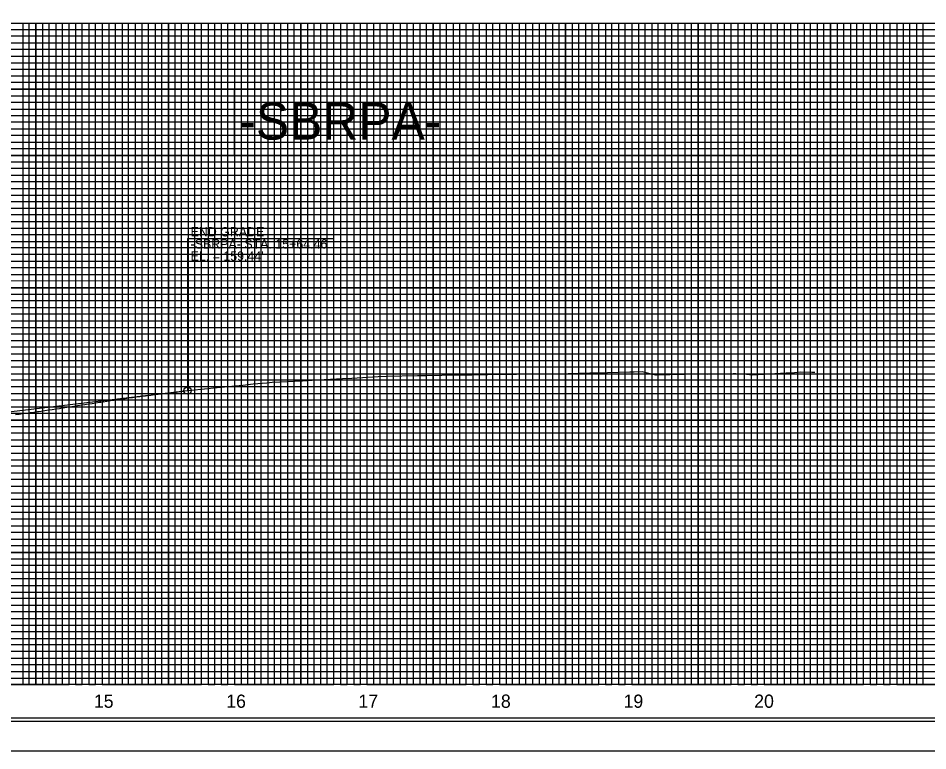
# Model space of a CAD drawing. Extents: x 573468 to 580768, y -57414 to -51768.
# Drawn here: x 579332 to 580019, y -57414 to -56860 of the extents above; entities that cross this region are included whole.
import ezdxf

# ---------------------------------------------------------------- set-up
doc = ezdxf.new("R2010")
doc.units = 0
for name, color, linetype in [('Exist Vertical Profile Ground Line', 7, 'Continuous'), ('Exist Vertical Profile Horizontal Axis Label Major', 7, 'Continuous'), ('Prop Grid Mask', 7, 'Continuous'), ('Prop PFL Text', 7, 'Continuous'), ('Prop Vertical Profile Grade', 7, 'Continuous'), ('Prop VPI Label', 7, 'Continuous'), ('Sheet Cutting Line CELL', 7, 'Continuous'), ('Sheet DOT Grid CELL', 7, 'Continuous'), ('Sheet Layout Profile Border Port 2', 7, 'Continuous'), ('Sheet Plot Border Inside CELL', 7, 'Continuous'), ('Sheet Plot Border Outside CELL', 7, 'Continuous'), ('Sheet Profile CELL', 7, 'Continuous'), ('Sheet Profile Grid Major CELL', 7, 'Continuous'), ('Sheet Profile Grid Middle CELL', 7, 'Continuous'), ('Sheet Profile Grid Minor CELL', 7, 'Continuous')]:
    doc.layers.add(name, color=color, linetype=linetype)

msp = doc.modelspace()

# ---------------------------------------------------------------- linework, layer by layer
at = {"layer": 'Exist Vertical Profile Ground Line'}
for points in [[(579365.05, -57154.41), (579365.65, -57154.32), (579368.42, -57153.92), (579371.18, -57153.52), (579372.22, -57153.37), (579373.95, -57153.08), (579376.71, -57152.63), (579379.57, -57152.17), (579382.24, -57151.77), (579385.01, -57151.36), (579387.77, -57150.95), (579390.54, -57150.54), (579393.31, -57150.13), (579394.3, -57149.99), (579396.07, -57149.71), (579398.84, -57149.28), (579400.55, -57149.01), (579401.6, -57148.86), (579404.37, -57148.47), (579407.13, -57148.07), (579409.9, -57147.68), (579412.66, -57147.29), (579415.43, -57146.91), (579418.19, -57146.52), (579420.96, -57146.14), (579423.72, -57145.75), (579426.49, -57145.37), (579427.84, -57145.19), (579429.26, -57145.02), (579432.02, -57144.69), (579434.79, -57144.36), (579437.55, -57144.04), (579440.32, -57143.71), (579443.08, -57143.39), (579445.85, -57143.07), (579448.61, -57142.76), (579449.25, -57142.68), (579451.38, -57142.41), (579454.14, -57142.05), (579456.91, -57141.69), (579457.5, -57141.61), (579459.67, -57141.37), (579475.09, -57139.65), (579479.32, -57139.11), (579501.55, -57137.23), (579509.31, -57136.33), (579519.62, -57135.47), (579523.72, -57134.99), (579546.45, -57133.82), (579553.68, -57133.4), (579576.75, -57132.21), (579583.65, -57131.8), (579603.7, -57130.77), (579609.88, -57130.41), (579633.45, -57130), (579639.84, -57129.88), (579663.64, -57129.47), (579669.8, -57129.36), (579674.4, -57129.28), (579698.51, -57129), (579704.4, -57128.93), (579708.02, -57128.88), (579732.32, -57128.6), (579733.3, -57128.59), (579738.84, -57128.53), (579763.46, -57127.85), (579768.59, -57127.8), (579793.62, -57127.11), (579796.85, -57127.07), (579803.01, -57126.9), (579811.94, -57129.08), (579813.1, -57129.38), (579813.92, -57129.39), (579822.16, -57129.17), (579823.92, -57129.11), (579833.6, -57128.82), (579834.9, -57128.78), (579845.06, -57128.3), (579845.71, -57128.3), (579851.29, -57128.76), (579852, -57128.82), (579856.05, -57128.57), (579857.12, -57128.56), (579861.44, -57128.6), (579862.9, -57128.69), (579868.03, -57128.62), (579871.83, -57128.49), (579873.8, -57128.35), (579877.34, -57128.57), (579879.8, -57128.61), (579881.86, -57128.86), (579884.16, -57129.11), (579886.28, -57129.31), (579911.68, -57127.88), (579913.57, -57127.87), (579915.66, -57127.77), (579922.19, -57127.14), (579931.1, -57127.47), (579933.49, -57127.47)], [(579329.7, -57159.39), (579332.47, -57159.03), (579335.23, -57158.66), (579338, -57158.3), (579340.76, -57157.93), (579341.43, -57157.85), (579343.53, -57157.55), (579346.29, -57157.17), (579347.15, -57157.05), (579349.06, -57156.76), (579351.82, -57156.35), (579354.59, -57155.94), (579357.36, -57155.53), (579360.12, -57155.13), (579362.89, -57154.73), (579365.05, -57154.41)]]:
    msp.add_lwpolyline(points, dxfattribs=at)
at = {"layer": 'Prop Grid Mask'}
msp.add_lwpolyline([(579495.21, -56913.55), (579645.21, -56913.55), (579645.21, -56963.55), (579495.21, -56963.55)], close=True, dxfattribs=at)
at = {"layer": 'Prop PFL Text'}
for q in [(579570.38, -57026.26), (579459.67, -57141.35)]:
    msp.add_line((579459.67, -57026.26), q, dxfattribs=at)
at = {"layer": 'Prop Vertical Profile Grade'}
msp.add_line((579305.21, -57159.61), (579459.67, -57141.35), dxfattribs=at)
at = {"layer": 'Prop VPI Label'}
msp.add_circle((579459.67, -57141.35), 2.75, dxfattribs=at)
at = {"layer": 'Sheet Cutting Line CELL'}
msp.add_line((578678.21, -57413.55), (580362.21, -57413.55), dxfattribs=at)
at = {"layer": 'Sheet DOT Grid CELL'}
for p, q in [((578845.21, -56863.55), (580345.1, -56863.55)), ((579345.21, -56863.55), (579345.21, -57363.55)), ((579395.21, -56863.55), (579395.21, -57363.55)), ((579445.21, -56863.55), (579445.21, -57363.55)), ((579495.21, -56863.55), (579495.21, -57363.55)), ((579545.21, -56863.55), (579545.21, -57363.55)), ((579595.21, -56863.55), (579595.21, -57363.55)), ((579645.21, -56863.55), (579645.21, -57363.55)), ((579695.21, -56863.55), (579695.21, -57363.55)), ((579745.21, -56863.55), (579745.21, -57363.55)), ((579795.21, -56863.55), (579795.21, -57363.55)), ((579845.21, -56863.55), (579845.21, -57363.55)), ((579895.21, -56863.55), (579895.21, -57363.55)), ((579945.21, -56863.55), (579945.21, -57363.55)), ((579995.21, -56863.55), (579995.21, -57363.55)), ((578845.21, -56913.55), (580345.1, -56913.55)), ((578845.21, -56963.55), (580345.1, -56963.55)), ((578845.21, -57013.55), (580345.1, -57013.55)), ((578845.21, -57063.55), (580345.1, -57063.55)), ((578845.21, -57113.55), (580345.1, -57113.55)), ((578845.21, -57163.55), (580345.1, -57163.55)), ((578845.21, -57213.55), (580345.1, -57213.55)), ((578845.21, -57263.55), (580345.1, -57263.55)), ((578845.21, -57313.55), (580345.1, -57313.55))]:
    msp.add_line(p, q, dxfattribs=at)
at = {"layer": 'Sheet Layout Profile Border Port 2'}
msp.add_lwpolyline([(578895.21, -56863.55), (580295.21, -56863.55), (580295.21, -57363.55), (578895.21, -57363.55)], close=True, dxfattribs=at)
at = {"layer": 'Sheet Plot Border Inside CELL'}
msp.add_lwpolyline([(578691.21, -57391.1), (580357.71, -57391.1), (580357.71, -56336), (578691.21, -56336)], close=True, dxfattribs=at)
at = {"layer": 'Sheet Plot Border Outside CELL'}
msp.add_lwpolyline([(578678.21, -57413.55), (580362.21, -57413.55), (580362.21, -56313.55), (578678.21, -56313.55)], close=True, dxfattribs=at)
at = {"layer": 'Sheet Profile CELL'}
for p, q in [((578845.21, -56863.55), (580345.21, -56863.55)), ((580345.21, -57363.55), (578845.21, -57363.55)), ((578845.21, -57388.55), (580345.21, -57388.55))]:
    msp.add_line(p, q, dxfattribs=at)
msp.add_lwpolyline([(580345.21, -56338.55), (578845.21, -56338.55), (578845.21, -57388.55), (580345.21, -57388.55)], close=True, dxfattribs=at)
at = {"layer": 'Sheet Profile Grid Major CELL'}
for p, q in [((579345.21, -56863.55), (579395.21, -56863.55)), ((579445.21, -56863.55), (579495.21, -56863.55)), ((579545.21, -56863.55), (579595.21, -56863.55)), ((579645.21, -56863.55), (579695.21, -56863.55)), ((579745.21, -56863.55), (579795.21, -56863.55)), ((579845.21, -56863.55), (579895.21, -56863.55)), ((579945.21, -56863.55), (579995.21, -56863.55))]:
    msp.add_line(p, q, dxfattribs=at)
for points in [[(579295.21, -57363.55), (579345.21, -57363.55), (579345.21, -56863.55), (579395.21, -56863.55), (579395.21, -57363.55), (579445.21, -57363.55), (579445.21, -56863.55), (579495.21, -56863.55), (579495.21, -57363.55), (579545.21, -57363.55), (579545.21, -56863.55), (579595.21, -56863.55), (579595.21, -57363.55), (579645.21, -57363.55), (579645.21, -56863.55), (579695.21, -56863.55), (579695.21, -57363.55), (579745.21, -57363.55), (579745.21, -56863.55), (579795.21, -56863.55), (579795.21, -57363.55), (579845.21, -57363.55), (579845.21, -56863.55), (579895.21, -56863.55), (579895.21, -57363.55), (579945.21, -57363.55), (579945.21, -56863.55), (579995.21, -56863.55), (579995.21, -57363.55), (580045.21, -57363.55)], [(580345.21, -56913.55), (578845.21, -56913.55)], [(580345.21, -56963.55), (578845.21, -56963.55), (578845.21, -57013.55), (580345.21, -57013.55)], [(580345.21, -57063.55), (578845.21, -57063.55), (578845.21, -57113.55), (580345.21, -57113.55)], [(580345.21, -57163.55), (578845.21, -57163.55), (578845.21, -57213.55), (580345.21, -57213.55)], [(580345.21, -57263.55), (578845.21, -57263.55), (578845.21, -57263.55), (578845.21, -57313.55), (580345.21, -57313.55)], [(580345.21, -57363.55), (578845.21, -57363.55)]]:
    msp.add_lwpolyline(points, dxfattribs=at)
at = {"layer": 'Sheet Profile Grid Middle CELL'}
for points in [[(579320.21, -57363.55), (579370.21, -57363.55), (579370.21, -56863.55), (579420.21, -56863.55), (579420.21, -57363.55), (579470.21, -57363.55), (579470.21, -57363.55), (579470.21, -56863.55), (579520.21, -56863.55), (579520.21, -57363.55), (579570.21, -57363.55), (579570.21, -56863.55), (579620.21, -56863.55), (579620.21, -57363.55), (579670.21, -57363.55), (579670.21, -56863.55), (579720.21, -56863.55), (579720.21, -57363.55), (579770.21, -57363.55), (579770.21, -56863.55), (579820.21, -56863.55), (579820.21, -57363.55), (579870.21, -57363.55), (579870.21, -56863.55), (579920.21, -56863.55), (579920.21, -57363.55), (579970.21, -57363.55), (579970.21, -56863.55), (580020.21, -56863.55)], [(578845.21, -56888.55), (580345.21, -56888.55)], [(580345.21, -56938.55), (578845.21, -56938.55), (578845.21, -56988.55), (580345.21, -56988.55)], [(580345.21, -57038.55), (578845.21, -57038.55), (578845.21, -57088.55), (580345.21, -57088.55)], [(580345.21, -57138.55), (578845.21, -57138.55), (578845.21, -57188.55), (580345.21, -57188.55)], [(580345.21, -57238.55), (578845.21, -57238.55), (578845.21, -57288.55), (580345.21, -57288.55)], [(580345.21, -57338.55), (578845.21, -57338.55)]]:
    msp.add_lwpolyline(points, dxfattribs=at)
at = {"layer": 'Sheet Profile Grid Minor CELL'}
for p, q in [((578895.21, -56868.55), (580295.21, -56868.55)), ((580295.21, -56873.55), (578895.21, -56873.55)), ((578895.21, -56878.55), (580295.21, -56878.55)), ((580295.21, -56883.55), (578895.21, -56883.55)), ((578895.21, -56893.55), (580295.21, -56893.55)), ((580295.21, -56898.55), (578895.21, -56898.55)), ((578895.21, -56903.55), (580295.21, -56903.55)), ((580295.21, -56908.55), (578895.21, -56908.55)), ((578895.21, -56918.55), (580295.21, -56918.55)), ((580295.21, -56923.55), (578895.21, -56923.55)), ((578895.21, -56928.55), (580295.21, -56928.55)), ((580295.21, -56933.55), (578895.21, -56933.55)), ((578895.21, -56943.55), (580295.21, -56943.55)), ((580295.21, -56948.55), (578895.21, -56948.55)), ((578895.21, -56953.55), (580295.21, -56953.55)), ((580295.21, -56958.55), (578895.21, -56958.55)), ((578895.21, -56968.55), (580295.21, -56968.55)), ((580295.21, -56973.55), (578895.21, -56973.55)), ((578895.21, -56978.55), (580295.21, -56978.55)), ((580295.21, -56983.55), (578895.21, -56983.55)), ((578895.21, -56993.55), (580295.21, -56993.55)), ((580295.21, -56998.55), (578895.21, -56998.55)), ((578895.21, -57003.55), (580295.21, -57003.55)), ((580295.21, -57008.55), (578895.21, -57008.55)), ((578895.21, -57018.55), (580295.21, -57018.55)), ((580295.21, -57023.55), (578895.21, -57023.55)), ((578895.21, -57028.55), (580295.21, -57028.55)), ((580295.21, -57033.55), (578895.21, -57033.55)), ((578895.21, -57043.55), (580295.21, -57043.55)), ((580295.21, -57048.55), (578895.21, -57048.55)), ((578895.21, -57053.55), (580295.21, -57053.55)), ((580295.21, -57058.55), (578895.21, -57058.4)), ((578895.21, -57068.55), (580295.21, -57068.55)), ((580295.21, -57073.55), (578895.21, -57073.55)), ((578895.21, -57078.55), (580295.21, -57078.55)), ((580295.21, -57083.55), (578895.21, -57083.55)), ((578895.21, -57093.55), (580295.21, -57093.55)), ((580295.21, -57098.55), (578895.21, -57098.55)), ((578895.21, -57103.55), (580295.21, -57103.55)), ((580295.21, -57108.55), (578895.21, -57108.55)), ((578895.21, -57118.55), (580295.21, -57118.55)), ((580295.21, -57123.55), (578895.21, -57123.55)), ((578895.21, -57128.55), (580295.21, -57128.55)), ((580295.21, -57133.55), (578895.21, -57133.55)), ((578895.21, -57143.55), (580295.21, -57143.55)), ((580295.21, -57148.55), (578895.21, -57148.55)), ((578895.21, -57153.55), (580295.21, -57153.55)), ((580295.21, -57158.55), (578895.21, -57158.55)), ((578895.21, -57168.55), (580295.21, -57168.55)), ((580295.21, -57173.55), (578895.21, -57173.55)), ((578895.21, -57178.55), (580295.21, -57178.55)), ((580295.21, -57183.55), (578895.21, -57183.55)), ((578895.21, -57193.55), (580295.21, -57193.55)), ((580295.21, -57198.55), (578895.21, -57198.55)), ((578895.21, -57203.55), (580295.21, -57203.55)), ((580295.21, -57208.55), (578895.21, -57208.55)), ((578895.21, -57218.55), (580295.21, -57218.55)), ((580295.21, -57223.55), (578895.21, -57223.55)), ((578895.21, -57228.55), (580295.21, -57228.55)), ((580295.21, -57233.55), (578895.21, -57233.55)), ((578895.21, -57243.55), (580295.21, -57243.55)), ((580295.21, -57248.55), (578895.21, -57248.55)), ((578895.21, -57253.55), (580295.21, -57253.55)), ((580295.21, -57258.55), (578895.21, -57258.55)), ((578895.21, -57268.55), (580295.21, -57268.55)), ((580295.21, -57273.55), (578895.21, -57273.55)), ((578895.21, -57278.55), (580295.21, -57278.55)), ((580295.21, -57283.55), (578895.21, -57283.55)), ((578895.21, -57293.55), (580295.21, -57293.55)), ((580295.21, -57298.55), (578895.21, -57298.55)), ((578895.21, -57303.55), (580295.21, -57303.55)), ((580295.21, -57308.55), (578895.21, -57308.55)), ((578895.21, -57318.55), (580295.21, -57318.55)), ((580295.21, -57323.55), (578895.21, -57323.55)), ((578895.21, -57328.55), (580295.21, -57328.55)), ((580295.21, -57333.55), (578895.21, -57333.55)), ((578895.21, -57343.55), (580295.21, -57343.55)), ((580295.21, -57348.55), (578895.21, -57348.55)), ((578895.21, -57353.55), (580295.21, -57353.55)), ((578895.21, -57358.55), (580295.21, -57358.55))]:
    msp.add_line(p, q, dxfattribs=at)
for points in [[(579330.21, -56863.55), (579335.21, -56863.55), (579335.21, -57363.55), (579340.21, -57363.55), (579340.21, -56863.55), (579350.21, -56863.55), (579350.21, -57363.55), (579355.21, -57363.55), (579355.21, -56863.55), (579360.21, -56863.55), (579360.21, -57363.55), (579365.21, -57363.55), (579365.21, -56863.55), (579375.21, -56863.55), (579375.21, -57363.55), (579380.21, -57363.55), (579380.21, -56863.55), (579385.21, -56863.55), (579385.21, -57363.55), (579390.21, -57363.55), (579390.21, -56863.55), (579400.21, -56863.55), (579400.21, -57363.55), (579405.21, -57363.55), (579405.21, -56863.55), (579410.21, -56863.55), (579410.21, -57363.55), (579415.21, -57363.55), (579415.21, -56863.55), (579425.21, -56863.55)], [(579425.21, -56863.55), (579425.21, -57363.55), (579430.21, -57363.55), (579430.21, -56863.55), (579435.21, -56863.55), (579435.21, -57363.55), (579440.21, -57363.55), (579440.21, -56863.55), (579450.21, -56863.55), (579450.21, -57363.55), (579455.21, -57363.55), (579455.21, -56863.55), (579460.21, -56863.55), (579460.21, -57363.55), (579465.21, -57363.55), (579465.21, -56863.55), (579475.21, -56863.55), (579475.21, -57363.55), (579480.21, -57363.55), (579480.21, -56863.55), (579485.21, -56863.55), (579485.21, -57363.55), (579490.21, -57363.55), (579490.21, -56863.55), (579500.21, -56863.55), (579500.21, -57363.55), (579505.21, -57363.55), (579505.21, -56863.55), (579510.21, -56863.55), (579510.21, -57363.55), (579515.21, -57363.55), (579515.21, -56863.55), (579525.21, -56863.55), (579525.21, -57363.55), (579530.21, -57363.55), (579530.21, -56863.55), (579535.21, -56863.55), (579535.21, -57363.55), (579540.21, -57363.55), (579540.21, -56863.55), (579550.21, -56863.55), (579550.21, -57363.55), (579550.21, -57363.55), (579555.21, -57363.55), (579555.21, -56863.55), (579560.21, -56863.55), (579560.21, -57363.55), (579565.21, -57363.55), (579565.21, -56863.55), (579575.21, -56863.55), (579575.21, -57363.55), (579580.21, -57363.55), (579580.21, -56863.55), (579585.21, -56863.55), (579585.21, -57363.55), (579590.21, -57363.55), (579590.21, -56863.55), (579600.21, -56863.55), (579600.21, -57363.55), (579605.21, -57363.55), (579605.21, -56863.55), (579610.21, -56863.55), (579610.21, -57363.55), (579615.21, -57363.55), (579615.21, -56863.55), (579625.21, -56863.55), (579625.21, -57363.55), (579630.21, -57363.55), (579630.21, -56863.55), (579635.21, -56863.55), (579635.21, -57363.55), (579640.21, -57363.55), (579640.21, -56863.55), (579650.21, -56863.55), (579650.21, -57363.55), (579655.21, -57363.55), (579655.21, -56863.55), (579660.21, -56863.55), (579660.21, -57363.55), (579665.21, -57363.55), (579665.21, -56863.55), (579675.21, -56863.55), (579675.21, -57363.55), (579680.21, -57363.55), (579680.21, -56863.55), (579685.21, -56863.55), (579685.21, -57363.55), (579690.21, -57363.55), (579690.21, -56863.55), (579700.21, -56863.55), (579700.21, -57363.55), (579704.91, -57363), (579705.21, -57363.55), (579705.21, -56863.55), (579710.21, -56863.55), (579710.21, -57363.55), (579715.21, -57363.55), (579715.21, -56863.55), (579725.21, -56863.55), (579725.21, -57363.55), (579730.21, -57363.55)], [(579730.21, -57363.55), (579730.21, -56863.55), (579735.21, -56863.55), (579735.21, -57363.55), (579740.21, -57363.55), (579740.21, -56863.55), (579750.21, -56863.55), (579750.21, -57363.55), (579755.21, -57363.55), (579755.21, -56863.55), (579760.21, -56863.55), (579760.21, -57363.55), (579765.21, -57363.55), (579765.21, -56863.55), (579775.21, -56863.55), (579775.21, -57363.55), (579780.21, -57363.55), (579780.21, -56863.55), (579785.21, -56863.55), (579785.21, -57363.55), (579790.21, -57363.55), (579790.21, -56863.55), (579800.21, -56863.55), (579800.21, -57363.55), (579805.21, -57363.55), (579805.21, -56863.55), (579810.21, -56863.55), (579810.21, -57363.55), (579815.21, -57363.55), (579815.21, -56863.55), (579825.21, -56863.55), (579825.21, -57363.55), (579830.21, -57363.55), (579830.21, -56863.55), (579835.21, -56863.55), (579835.21, -57363.55), (579840.21, -57363.55), (579840.21, -56863.55), (579850.21, -56863.55), (579850.21, -57363.55), (579855.21, -57363.55), (579855.21, -56863.55), (579860.21, -56863.55), (579860.21, -57363.55), (579865.21, -57363.55), (579865.21, -56863.55), (579875.21, -56863.55), (579875.21, -57363.55), (579880.21, -57363.55), (579880.21, -56863.55), (579885.21, -56863.55), (579885.21, -57363.55), (579890.21, -57363.55), (579890.21, -56863.55), (579900.21, -56863.55), (579900.21, -57363.55), (579905.21, -57363.55), (579905.21, -56863.55), (579910.21, -56863.55), (579910.21, -57363.55), (579915.21, -57363.55), (579915.21, -56863.55), (579925.21, -56863.55), (579925.21, -57363.55), (579930.21, -57363.55), (579930.21, -56863.55), (579935.21, -56863.55), (579935.21, -57363.55), (579940.21, -57363.55), (579940.21, -56863.55), (579950.21, -56863.55), (579950.21, -57363.55), (579955.21, -57363.55), (579955.21, -56863.55), (579960.21, -56863.55), (579960.21, -57363.55), (579965.21, -57363.55), (579965.21, -56863.55), (579975.21, -56863.55), (579975.21, -57363.55), (579980.21, -57363.55), (579980.21, -56863.55), (579985.21, -56863.55), (579985.21, -57363.55), (579990.21, -57363.55), (579990.21, -56863.55), (580000.21, -56863.55), (580000.21, -57363.55), (580005.21, -57363.55), (580005.21, -56863.55), (580010.21, -56863.55), (580010.21, -57363.55), (580015.21, -57363.55), (580015.21, -56863.55), (580025.21, -56863.55)]]:
    msp.add_lwpolyline(points, dxfattribs=at)

# ---------------------------------------------------------------- texts
at = {"layer": 'Exist Vertical Profile Horizontal Axis Label Major'}
for s, p in [('15', (579388.96, -57381.05)), ('16', (579488.9, -57381.05)), ('17', (579588.75, -57381.05)), ('18', (579688.88, -57381.05)), ('19', (579788.92, -57381.05)), ('20', (579887.6, -57381.05))]:
    msp.add_text(s, height=10, dxfattribs=at).set_placement(p)
at = {"layer": 'Prop PFL Text'}
for s, height, p in [('-SBRPA-', 28.125, (579498.81, -56951.65)), ('END GRADE', 7, (579462.01, -57024.8)), ('-SBRPA- STA. 15+64.46', 7, (579462.01, -57033.98)), ("EL. = 159.44'", 7, (579462.01, -57043.16))]:
    msp.add_text(s, height=height, dxfattribs=at).set_placement(p)

doc.saveas('drawing.dxf')
